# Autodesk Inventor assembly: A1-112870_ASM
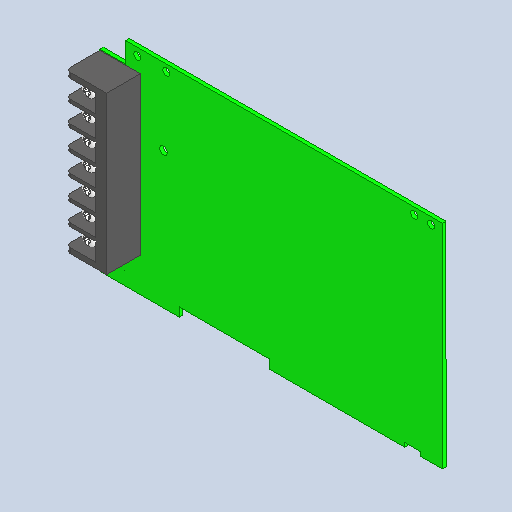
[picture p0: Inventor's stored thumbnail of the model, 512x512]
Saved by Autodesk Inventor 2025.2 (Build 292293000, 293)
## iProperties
Created: 2025-04
Part Number: A1-112870_ASM
Description: NOT SPECIFIED
Document SubType Name: Assembly
Designer: BennF
Author: BennF
Revision Number: 5LAST_VERSION
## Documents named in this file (3)
- C:\Users\BennF\Nextcloud\Benutzer\CNC JarBeRi\existing parts\Electronics\Powersupply LRS-150-24\LRS-150(230808)\LRS-150(230808)\A1-112870_ASM.iam
- C:\Users\BennF\Nextcloud\Benutzer\CNC JarBeRi\existing parts\Electronics\Powersupply LRS-150-24\LRS-150(230808)\LRS-150(230808)\PCB.ipt
- C:\Users\BennF\Nextcloud\Benutzer\CNC JarBeRi\existing parts\Electronics\Powersupply LRS-150-24\LRS-150(230808)\LRS-150(230808)\TN_1_1_1_1_1.ipt
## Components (2 placed, 2 different names)
1. PCB_25
2. TN_1_1_1_1_1_26
